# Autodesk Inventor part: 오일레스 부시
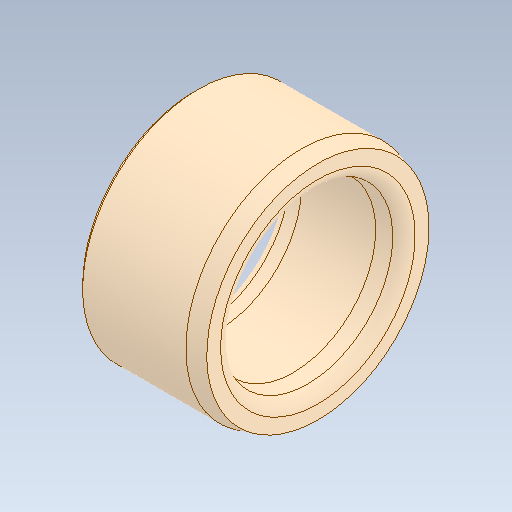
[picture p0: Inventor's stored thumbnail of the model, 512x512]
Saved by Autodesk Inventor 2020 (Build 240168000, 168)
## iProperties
Created: 2024-07
Part Number: 오일레스 부시
Material: 일반
Document SubType Name: Modeling
Designer: oem
Density: 1 g/cm^3
Appearance: 기본값
Mass: 4.32215 g
Surface Area: 26.8882 cm^2
Volume: 4.32215 cm^3
Sending System: Autodesk Inventor 2025
Preprocessor: ST-DEVELOPER v20
Author: jhkim
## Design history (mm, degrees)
feature "솔리드1"
node "솔리드2"
